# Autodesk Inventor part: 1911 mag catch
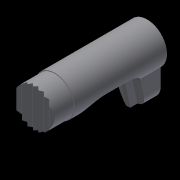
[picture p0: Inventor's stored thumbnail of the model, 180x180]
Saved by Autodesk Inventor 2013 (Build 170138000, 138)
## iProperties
Created: 2013-02
Part Number: 1911 mag catch
Material: Generic
Document SubType Name: Modeling
Designer: John
Density: 1 g/cm^3
Author: John
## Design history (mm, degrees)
sketch "Sketch1"
  geometry: L1 (2.731, -6.172)-(2.731, -2.836); L2 (-2.731, -6.172)-(-2.731, -2.836); C1 r 3.937 at (0, 0); A1 r 3.937 centre (0, 0) between (2.731, -2.836) and (-2.731, -2.836); A2 r 2.731 centre (0, -6.172) between (-2.731, -6.172) and (2.731, -6.172); 2 further points
  constraints: 4 end point, 4 point on circle, 3 centre point, 2 coincident, 1 concentric, 1 parallel
  dimensions: "d0" = 7.874 diameter of A1
extrude "Extrusion1" new body sketch "Sketch1" distance "d3" = 21.8694; taper "d4" = 0 deg
sketch "Sketch2"
  geometry: C1 r 3.937 at (0, 0) reference; C2 r 3.664 at (0, 0)
  constraints: 1 centre point, 1 coincident
  dimensions: "d5" = 7.3279 diameter of C2
extrude "Extrusion2" cut sketch "Sketch2" distance "d6" = 4.191; taper "d7" = 0 deg
extrude "Extrusion3" join sketch "Sketch1" distance "d8" = 7.62; taper "d9" = 0 deg
workplane "Work Plane1"
sketch "Sketch4"
  geometry: L1 (3.937, 0)-(3.937, 17.678) reference; L2 (-3.937, 17.678)-(3.937, 17.678) reference; L3 (3.937, 17.678)-(-0.94, 17.678); L4 (-3.937, 17.678)-(-3.937, 16.916); L5 (-0.94, 11.524)-(-0.94, 8.061); L6 (-3.937, 17.678)-(-9.412, 17.678); L7 (-8.903, 0)-(-8.903, 7.62) reference; L8 (-8.903, 3.797)-(-3.455, 4.955) reference; L9 (-8.903, 7.62)-(-3.937, 16.916); A1 r 6.35 centre (-7.29, 11.524) between (-0.94, 11.524) and (-3.937, 16.916); A2 r 3.175 centre (-4.115, 8.061) between (-3.455, 4.955) and (-0.94, 8.061); 1 further point
  constraints: 12 end point, 4 point on circle, 3 tangent, 2 centre point, 2 perpendicular, 2 point on line, 1 parallel, 1 vertical, 1 other
  dimensions: "d15" = 3.175 radius of A2
extrude "Extrusion4" cut sketch "Sketch4" distance "d16" = 17.78; taper "d17" = 0 deg
workplane "Work Plane2"
sketch "Sketch6"
  geometry: L1 (-3.455, 4.955)-(-6.172, 4.378) reference; L2 (-8.903, 3.797)-(-6.172, 4.378) reference; A1 r 3.175 centre (-4.115, 8.061) between (-3.455, 4.955) and (-2.836, 5.155) reference; 2 further points
  constraints: 1 other
sketch "Sketch5"
  geometry: L1 (4.364, 1.653)-(0, 3.886); L2 (4.364, 1.653)-(4.364, 5.089); L3 (4.364, 5.089)-(0, 5.089); L4 (0, 5.089)-(0, 3.886); 1 further point
  constraints: 8 end point
sweep "Sweep1" sketch "Sketch5" dims "d19" = 0
sketch "Sketch7"
  geometry: L1 (0, 0)-(-0.635, 0); L2 (-0.635, 2.413)-(-0.635, 3.813); L3 (-2.731, 4.378)-(-5.507, 4.378); 2 further points; 2 other entities
  constraints: 6 end point, 1 horizontal, 1 perpendicular, 6 other
  dimensions: "d20" = 0.635 distance of L1.start L1.end
sweep "Sweep2" sketch "Sketch7" dims "d22" = 0
sketch "Sketch8"
  geometry: L1 (0, 21.869)-(0.508, 21.361) reference; L2 (0, 21.869)-(-0.508, 21.361) reference; L3 (0.508, 21.361)-(-0.508, 21.361); L4 (-1.052, 21.869)-(-0.544, 21.361) reference; L5 (-1.052, 21.869)-(-1.56, 21.361) reference; L6 (-0.544, 21.361)-(-1.56, 21.361); L7 (-2.103, 21.869)-(-1.595, 21.361) reference; L8 (-2.103, 21.869)-(-2.611, 21.361) reference; L9 (-1.595, 21.361)-(-2.611, 21.361); L10 (-3.155, 21.869)-(-2.647, 21.361) reference; L11 (-3.155, 21.869)-(-3.663, 21.361) reference; L12 (-2.647, 21.361)-(-3.663, 21.361); L13 (1.052, 21.869)-(1.56, 21.361) reference; L14 (1.052, 21.869)-(0.544, 21.361) reference; L15 (1.56, 21.361)-(0.544, 21.361); L16 (0, 21.869)-(0.508, 21.361) reference; L17 (0, 21.869)-(-0.508, 21.361) reference; L18 (0.508, 21.361)-(-0.508, 21.361); L19 (-1.052, 21.869)-(-0.544, 21.361) reference; L20 (-1.052, 21.869)-(-1.56, 21.361) reference; L21 (-0.544, 21.361)-(-1.56, 21.361); L22 (-2.103, 21.869)-(-1.595, 21.361) reference; L23 (-2.103, 21.869)-(-2.611, 21.361) reference; L24 (-1.595, 21.361)-(-2.611, 21.361); L25 (2.103, 21.869)-(2.611, 21.361) reference; L26 (2.103, 21.869)-(1.595, 21.361) reference; L27 (2.611, 21.361)-(1.595, 21.361); L28 (1.052, 21.869)-(1.56, 21.361) reference; L29 (1.052, 21.869)-(0.544, 21.361) reference; L30 (1.56, 21.361)-(0.544, 21.361); L31 (0, 21.869)-(0.508, 21.361) reference; L32 (0, 21.869)-(-0.508, 21.361) reference; L33 (0.508, 21.361)-(-0.508, 21.361); L34 (-1.052, 21.869)-(-0.544, 21.361) reference; L35 (-1.052, 21.869)-(-1.56, 21.361) reference; L36 (-0.544, 21.361)-(-1.56, 21.361); L37 (3.155, 21.869)-(3.663, 21.361) reference; L38 (3.155, 21.869)-(2.647, 21.361) reference; L39 (3.663, 21.361)-(2.647, 21.361); L40 (2.103, 21.869)-(2.611, 21.361) reference; L41 (2.103, 21.869)-(1.595, 21.361) reference; L42 (2.611, 21.361)-(1.595, 21.361); L43 (1.052, 21.869)-(1.56, 21.361) reference; L44 (1.052, 21.869)-(0.544, 21.361) reference; L45 (1.56, 21.361)-(0.544, 21.361); L46 (0, 21.869)-(0.508, 21.361) reference; L47 (0, 21.869)-(-0.508, 21.361) reference; L48 (0.508, 21.361)-(-0.508, 21.361); L49 (2.647, 21.361)-(2.611, 21.361); L50 (1.595, 21.361)-(1.56, 21.361); L51 (0.544, 21.361)-(0.508, 21.361); L52 (-0.508, 21.361)-(-0.544, 21.361); L53 (-1.56, 21.361)-(-1.595, 21.361); L54 (-2.611, 21.361)-(-2.647, 21.361); L55 (3.663, 21.361)-(3.971, 21.361); L56 (3.971, 21.361)-(3.971, 22.094); L57 (3.971, 22.094)-(-3.869, 22.094); L58 (-3.869, 22.094)-(-3.869, 21.361); L59 (-3.869, 21.361)-(-3.663, 21.361); 1 further point
  constraints: 118 end point, 10 collinear, 3 horizontal, 2 parallel, 1 perpendicular, 92 other
  dimensions: "d33" = 1.05156 distance of L1.start L4.start; "d36" = 1.05156 distance of L1.start L13.start
extrude "Extrusion5" cut sketch "Sketch8" distance "d39" = 25.4; taper "d40" = 0 deg
sketch "Sketch10"
  geometry: L1 (2.731, -2.836)-(2.731, -6.172) reference; L2 (-2.731, -6.172)-(-2.731, -2.836) reference; L3 (2.604, -2.782)-(2.604, -6.172); L4 (-2.604, -6.172)-(-2.604, -2.782); A1 r 3.937 centre (0, 0) between (2.731, -2.836) and (-2.731, -2.836) reference; A2 r 2.731 centre (0, -6.172) between (-2.731, -6.172) and (2.731, -6.172) reference; A3 r 3.81 centre (0, 0) between (2.604, -2.782) and (-2.604, -2.782); A4 r 2.604 centre (0, -6.045) between (-2.604, -6.045) and (2.604, -6.045); 1 further point
  constraints: 4 end point, 4 point on circle, 2 centre point, 2 point on line, 1 tangent, 1 other
  dimensions: "d47" = 0.127 distance between parallel lines of L1 L3
extrude "Extrusion8" cut sketch "Sketch10" distance "d48" = 25.4; taper "d49" = 0 deg
sketch "Sketch12"
  geometry: L1 (2.604, -2.953)-(2.604, -2.782) reference; L2 (-2.604, -2.782)-(-2.604, -2.953) reference; C1 r 3.664 at (0, 0) reference; C2 r 3.81 at (0, 0); A1 r 3.81 centre (0, 0) between (2.604, -2.782) and (-2.604, -2.782) reference; A2 r 3.937 centre (0, 0) between (-2.604, -2.953) and (2.604, -2.953) reference
  constraints: 1 centre point, 1 coincident, 1 concentric
extrude "Extrusion9" cut sketch "Sketch12" stored distance "d51" = 25.4; taper "d52" = 0 deg
body "Solid1"
